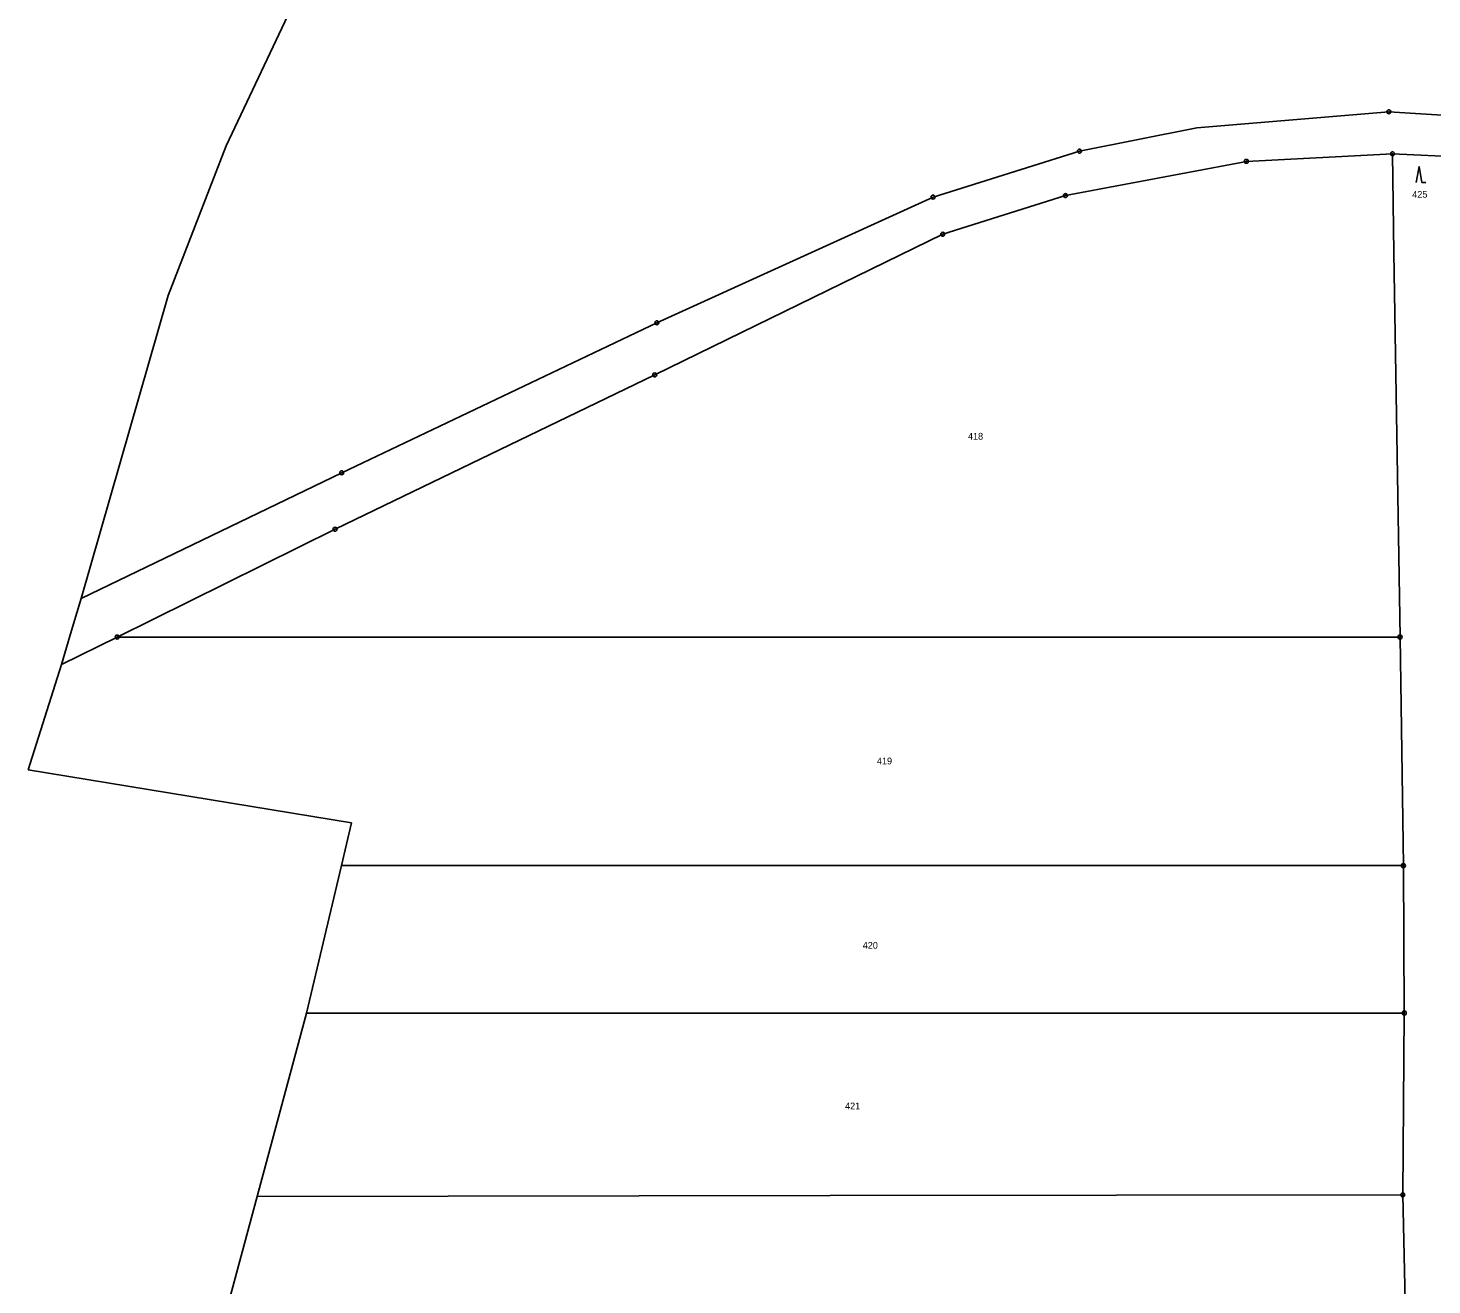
# Model space of a CAD drawing. Extents: x -759947 to -757003, y -1019641 to -1017100.
# Drawn here: x -759916.7 to -759564.7, y -1018113.8 to -1017798.6 of the extents above; entities that cross this region are included whole.
import ezdxf

# ---------------------------------------------------------------- set-up
doc = ezdxf.new("R2010")
doc.units = 0
doc.header["$LTSCALE"] = 0.68
for name, color, linetype, lineweight in [('1', 7, 'Continuous', 25), ('3', 7, 'Continuous', 25), ('8', 7, 'Continuous', 25)]:
    doc.layers.add(name, color=color, linetype=linetype, lineweight=lineweight)
doc.layers.add('2', color=7, linetype='Continuous')

msp = doc.modelspace()

# ---------------------------------------------------------------- linework, layer by layer
at = {"layer": '1'}
for p, q in [((-759867.03, -1017828.11), (-759836.64, -1017763.67)), ((-759575.53, -1017819.56), (-759623.7, -1017823.56)), ((-759541.73, -1017821.69), (-759575.53, -1017819.56)), ((-759623.7, -1017823.56), (-759653.1, -1017829.44)), ((-759881.61, -1017865.6), (-759867.03, -1017828.11)), ((-759653.1, -1017829.44), (-759689.82, -1017840.96)), ((-759656.61, -1017840.58), (-759611.26, -1017831.99)), ((-759611.26, -1017831.99), (-759574.62, -1017830.1)), ((-759574.62, -1017830.1), (-759574.3, -1017854.92)), ((-759574.62, -1017830.1), (-759542.95, -1017831.56)), ((-759759.05, -1017872.47), (-759689.82, -1017840.96)), ((-759687.38, -1017850.26), (-759656.61, -1017840.58)), ((-759759.6, -1017885.55), (-759687.38, -1017850.26)), ((-759574.3, -1017854.92), (-759572.74, -1017951.28)), ((-759903.37, -1017941.61), (-759881.61, -1017865.6)), ((-759838.07, -1017910.09), (-759759.05, -1017872.47)), ((-759839.73, -1017924.25), (-759759.6, -1017885.55)), ((-759903.37, -1017941.61), (-759838.07, -1017910.09)), ((-759894.35, -1017951.28), (-759839.73, -1017924.25)), ((-759905.77, -1017949.63), (-759903.37, -1017941.61)), ((-759908.34, -1017958.21), (-759905.77, -1017949.63)), ((-759894.35, -1017951.28), (-759908.34, -1017958.21)), ((-759733.54, -1017951.28), (-759894.35, -1017951.28)), ((-759572.74, -1017951.28), (-759733.54, -1017951.28)), ((-759572.74, -1017951.28), (-759571.89, -1018008.61)), ((-759916.69, -1017984.62), (-759908.34, -1017958.21)), ((-759835.58, -1017997.87), (-759916.69, -1017984.62)), ((-759838.12, -1018008.61), (-759835.58, -1017997.87)), ((-759846.87, -1018045.58), (-759838.12, -1018008.61)), ((-759838.12, -1018008.61), (-759705, -1018008.61)), ((-759705, -1018008.61), (-759571.89, -1018008.61)), ((-759571.89, -1018008.61), (-759571.67, -1018045.58)), ((-759859.24, -1018091.55), (-759846.87, -1018045.58)), ((-759709.27, -1018045.58), (-759846.87, -1018045.58)), ((-759571.67, -1018045.58), (-759709.27, -1018045.58)), ((-759572.05, -1018091.18), (-759571.67, -1018045.58)), ((-759872.99, -1018142.64), (-759859.24, -1018091.55)), ((-759859.24, -1018091.55), (-759715.64, -1018091.36)), ((-759715.64, -1018091.36), (-759572.05, -1018091.18)), ((-759572.05, -1018091.18), (-759570.19, -1018169.88))]:
    msp.add_line(p, q, dxfattribs=at)
at = {"layer": '3'}
msp.add_line((-759567.23, -1017837.31), (-759566.234, -1017837.31), dxfattribs=at)
msp.add_lwpolyline([(-759567.23, -1017837.31), (-759567.98, -1017833.31), (-759568.73, -1017837.31)], dxfattribs=at)
at = {"layer": '8'}
for centre, radius in [((-759575.53, -1017819.5599), 0.5), ((-759575.53, -1017819.5599), 0.0303), ((-759653.1, -1017829.4399), 0.5), ((-759653.1, -1017829.4399), 0.0303), ((-759611.26, -1017831.9899), 0.5), ((-759611.26, -1017831.9899), 0.0303), ((-759574.62, -1017830.0999), 0.5), ((-759574.62, -1017830.0999), 0.0303), ((-759689.82, -1017840.9599), 0.5), ((-759689.82, -1017840.9599), 0.0303), ((-759656.61, -1017840.5799), 0.5), ((-759656.61, -1017840.5799), 0.0303), ((-759687.38, -1017850.2599), 0.5), ((-759687.38, -1017850.2599), 0.0303), ((-759759.05, -1017872.4699), 0.5), ((-759759.05, -1017872.4699), 0.0303), ((-759759.6, -1017885.5499), 0.5), ((-759759.6, -1017885.5499), 0.0303), ((-759838.07, -1017910.0899), 0.5), ((-759838.07, -1017910.0899), 0.0303), ((-759839.73, -1017924.2499), 0.5), ((-759839.73, -1017924.2499), 0.0303), ((-759894.35, -1017951.2799), 0.5), ((-759894.35, -1017951.2799), 0.0303), ((-759572.74, -1017951.2799), 0.5), ((-759572.74, -1017951.2799), 0.0303), ((-759571.89, -1018008.6099), 0.5), ((-759571.89, -1018008.6099), 0.0303), ((-759571.67, -1018045.5799), 0.5), ((-759571.67, -1018045.5799), 0.0303), ((-759572.05, -1018091.1799), 0.5), ((-759572.05, -1018091.1799), 0.0303)]:
    msp.add_circle(centre, radius, dxfattribs=at)

# ---------------------------------------------------------------- texts
at = {"layer": '2'}
for s, p in [('425', (-759569.67, -1017841.115)), ('418', (-759681.05, -1017901.785)), ('419', (-759703.88, -1017983.215)), ('420', (-759707.44, -1018029.445)), ('421', (-759711.87, -1018069.735))]:
    msp.add_text(s, height=1.7, dxfattribs=at).set_placement(p)

doc.saveas('drawing.dxf')
